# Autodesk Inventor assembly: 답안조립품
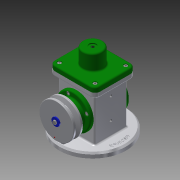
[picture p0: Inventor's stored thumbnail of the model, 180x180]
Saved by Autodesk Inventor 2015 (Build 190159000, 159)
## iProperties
Created: 2019-08
Part Number: 답안조립품
Document SubType Name: Assembly
Designer: CAD-08
Author: CAD-08
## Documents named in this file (18)
- C:\Users\CAD-08\Desktop\490804V1027\답안조립품.iam
- C:\Users\CAD-08\Desktop\490804V1027\E-링.ipt
- C:\Users\CAD-08\Desktop\490804V1027\V-벨트풀리.ipt
- C:\Users\CAD-08\Desktop\490804V1027\덮개.ipt
- C:\Users\CAD-08\Desktop\490804V1027\뒤커버.ipt
- C:\Users\CAD-08\Desktop\490804V1027\링크.ipt
- C:\Users\CAD-08\Desktop\490804V1027\베어링 17 x 40 x 12.ipt
- C:\Users\CAD-08\Desktop\490804V1027\본체.ipt
- C:\Users\CAD-08\Desktop\490804V1027\볼트 M4 x 8.ipt
- C:\Users\CAD-08\Desktop\490804V1027\볼트 M4 x 10.ipt
- C:\Users\CAD-08\Desktop\490804V1027\슬라이더.ipt
- C:\Users\CAD-08\Desktop\490804V1027\앞커버.ipt
- C:\Users\CAD-08\Desktop\490804V1027\오일 실 17 30 8.ipt
- C:\Users\CAD-08\Desktop\490804V1027\와셔 4x16.ipt
- C:\Users\CAD-08\Desktop\490804V1027\클레비스 핀 6 x 22.ipt
- 클레비스 핀 6 x 22.ipt
- C:\Users\CAD-08\Desktop\490804V1027\키 4 x 4 x 12.ipt
- C:\Users\CAD-08\Desktop\490804V1027\편심축.ipt
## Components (2 placed, 2 different names)
1. E-링:1
2. V-벨트풀리:1 — 각도:2
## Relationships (1: Angle 1)
- 각도:2 [Angle]: V-벨트풀리:1
